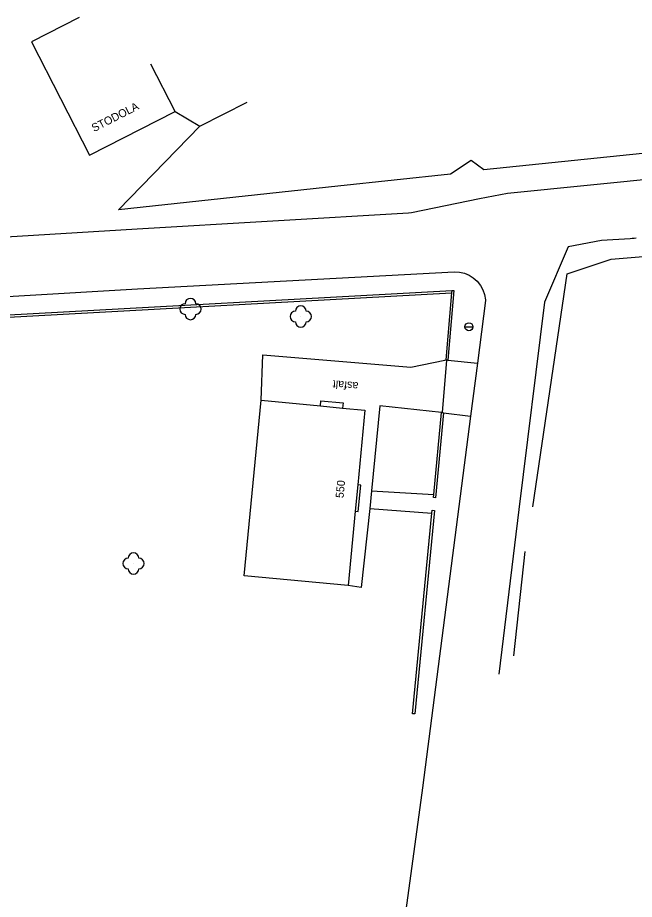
# Model space of a CAD drawing. Extents: x -545714 to -535419, y -1201788 to -1194297.
# Drawn here: x -535647.8 to -535590.1, y -1201668.6 to -1201586 of the extents above; entities that cross this region are included whole.
import ezdxf

# ---------------------------------------------------------------- set-up
doc = ezdxf.new("R2010")
doc.units = 0
for name, color, linetype in [('Vrstva 10', 7, 'Continuous'), ('Vrstva 11', 7, 'Continuous'), ('Vrstva 12', 7, 'Continuous'), ('Vrstva 15', 7, 'Continuous'), ('Vrstva 4', 7, 'Continuous'), ('Vrstva 8', 7, 'Continuous')]:
    doc.layers.add(name, color=color, linetype=linetype)

msp = doc.modelspace()

# ---------------------------------------------------------------- linework, layer by layer
at = {"layer": 'Vrstva 10'}
msp.add_line((-535605.935, -1201614.93), (-535605.185, -1201614.93), dxfattribs=at)
for points in [[(-535572.12, -1201588.65), (-535571.35, -1201590.42), (-535577.76, -1201593.75), (-535587.2, -1201598.48), (-535604.18, -1201600.22)], [(-535630.75, -1201596.13), (-535626.34, -1201593.87)], [(-535633.08, -1201594.77), (-535630.75, -1201596.13)], [(-535604.18, -1201600.22), (-535605.35, -1201599.35), (-535607.29, -1201600.63), (-535617.85, -1201601.75), (-535638.39, -1201603.96), (-535630.75, -1201596.13)], [(-535592.23, -1201608.58), (-535584.33, -1201607.95), (-535556.13, -1201605.24)], [(-535599.58, -1201631.8), (-535596.35, -1201609.97), (-535592.23, -1201608.58)], [(-535649.24, -1201614.05), (-535607.18, -1201611.74)], [(-535649.22, -1201613.85), (-535607.16, -1201611.54)], [(-535607.18, -1201611.74), (-535607.73, -1201618.04)], [(-535607.16, -1201611.54), (-535606.96, -1201611.53), (-535607.53, -1201618.06)], [(-535607.16, -1201611.54), (-535607.18, -1201611.74)], [(-535608.04, -1201622.97), (-535607.64, -1201618.05)], [(-535607.73, -1201618.04), (-535607.64, -1201618.05)], [(-535607.53, -1201618.06), (-535607.64, -1201618.05)], [(-535607.93, -1201622.98), (-535608.68, -1201630.95), (-535608.88, -1201630.92), (-535608.85, -1201630.64)], [(-535608.85, -1201630.64), (-535608.13, -1201622.96)], [(-535608.13, -1201622.96), (-535608.04, -1201622.97)], [(-535608.04, -1201622.97), (-535607.93, -1201622.98)], [(-535610.64, -1201651.2), (-535610.84, -1201651.21), (-535609.02, -1201632.39)], [(-535609.02, -1201632.39), (-535608.99, -1201632.12), (-535608.79, -1201632.14), (-535610.64, -1201651.2)], [(-535601.35, -1201645.78), (-535600.29, -1201635.98)]]:
    msp.add_lwpolyline(points, dxfattribs=at)
msp.add_circle((-535605.56, -1201614.93), 0.375, dxfattribs=at)
at = {"layer": 'Vrstva 11'}
for points in [[(-535586.73, -1201600.91), (-535601.96, -1201602.45), (-535604.58, -1201602.94), (-535610.94, -1201604.25), (-535611.21, -1201604.27), (-535636.62, -1201605.79), (-535670.91, -1201607.88)], [(-535593.16, -1201606.83), (-535596.27, -1201607.45), (-535598.47, -1201612.63), (-535600.88, -1201632.06), (-535602.77, -1201647.49)], [(-535589.91, -1201606.63), (-535590.1, -1201606.65), (-535590.29, -1201606.67), (-535590.47, -1201606.69), (-535593.16, -1201606.83)], [(-535670.5, -1201613.38), (-535636.6, -1201611.38), (-535606.94, -1201609.77), (-535606.46, -1201609.81), (-535605.99, -1201609.92), (-535605.55, -1201610.1), (-535605.15, -1201610.35), (-535604.79, -1201610.67), (-535604.49, -1201611.05), (-535604.25, -1201611.46), (-535604.09, -1201611.92), (-535604.01, -1201612.39), (-535604, -1201612.47), (-535604.76, -1201618.34)], [(-535625.02, -1201621.81), (-535624.85, -1201617.57), (-535610.99, -1201618.72), (-535607.83, -1201618.05), (-535607.73, -1201618.04)], [(-535607.53, -1201618.06), (-535604.76, -1201618.34)], [(-535604.76, -1201618.34), (-535605.4, -1201623.3)], [(-535619.47, -1201622.35), (-535619.43, -1201621.87), (-535617.35, -1201622.07), (-535617.4, -1201622.55)], [(-535608.13, -1201622.96), (-535613.9, -1201622.33), (-535614.7, -1201630.29)], [(-535605.4, -1201623.3), (-535609.91, -1201658.13), (-535616.63, -1201707.41), (-535624.28, -1201765.57), (-535626.89, -1201785.62), (-535627.19, -1201786.05), (-535627.78, -1201786.76), (-535628.42, -1201787.43), (-535629.12, -1201788.03), (-535629.31, -1201788.17)], [(-535607.93, -1201622.98), (-535605.4, -1201623.3)], [(-535616.21, -1201632.2), (-535615.92, -1201632.23), (-535615.68, -1201629.77), (-535615.98, -1201629.74)], [(-535614.7, -1201630.29), (-535614.85, -1201631.95)], [(-535614.7, -1201630.29), (-535608.85, -1201630.64)], [(-535614.85, -1201631.95), (-535615.65, -1201639.36), (-535616.86, -1201639.18)], [(-535614.85, -1201631.95), (-535609.02, -1201632.39)]]:
    msp.add_lwpolyline(points, dxfattribs=at)
at = {"layer": 'Vrstva 12'}
for centre in [(-535631.64, -1201613.27), (-535621.31, -1201613.97), (-535636.97, -1201637.11)]:
    msp.add_circle(centre, 0.0005, dxfattribs=at)
for centre, start, end in [((-535631.64, -1201612.77), 0, 179.99999), ((-535632.14, -1201613.27), 89.99999, 269.99999), ((-535631.14, -1201613.27), 270, 89.99999), ((-535621.81, -1201613.97), 89.99999, 269.99999), ((-535621.31, -1201613.47), 0, 179.99999), ((-535620.81, -1201613.97), 270, 89.99999), ((-535631.64, -1201613.77), 179.99999, 359.99999), ((-535621.31, -1201614.47), 179.99999, 359.99999), ((-535637.47, -1201637.11), 89.99999, 269.99999), ((-535636.97, -1201636.61), 0, 179.99999), ((-535636.47, -1201637.11), 270, 89.99999), ((-535636.97, -1201637.61), 179.99999, 359.99999)]:
    msp.add_arc(centre, 0.5, start, end, dxfattribs=at)
at = {"layer": 'Vrstva 4'}
for points in [[(-535642.06, -1201585.96), (-535646.51, -1201588.24), (-535641.1, -1201598.86), (-535633.08, -1201594.77)], [(-535633.08, -1201594.77), (-535635.36, -1201590.32)], [(-535616.86, -1201639.18), (-535626.62, -1201638.27), (-535625.02, -1201621.81)], [(-535625.02, -1201621.81), (-535619.47, -1201622.35)], [(-535619.47, -1201622.35), (-535617.4, -1201622.55)], [(-535617.4, -1201622.55), (-535615.32, -1201622.75), (-535615.98, -1201629.74)], [(-535615.98, -1201629.74), (-535616.21, -1201632.2)], [(-535616.21, -1201632.2), (-535616.86, -1201639.18)]]:
    msp.add_lwpolyline(points, dxfattribs=at)

# ---------------------------------------------------------------- texts
at = {"layer": 'Vrstva 15'}
for s, rotation, p in [('STODOLA', 27.04, (-535640.66, -1201596.69)), ('asfalt', 175.26, (-535615.89, -1201620.14))]:
    msp.add_text(s, height=0.75, rotation=rotation, dxfattribs=at).set_placement(p)
at = {"layer": 'Vrstva 8'}
msp.add_text('550', height=0.75, rotation=84.40001, dxfattribs=at).set_placement((-535617.31, -1201631.01))

doc.saveas('drawing.dxf')
